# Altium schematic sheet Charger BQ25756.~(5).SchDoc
size A3; SheetNumber: 6; SheetTotal: 7
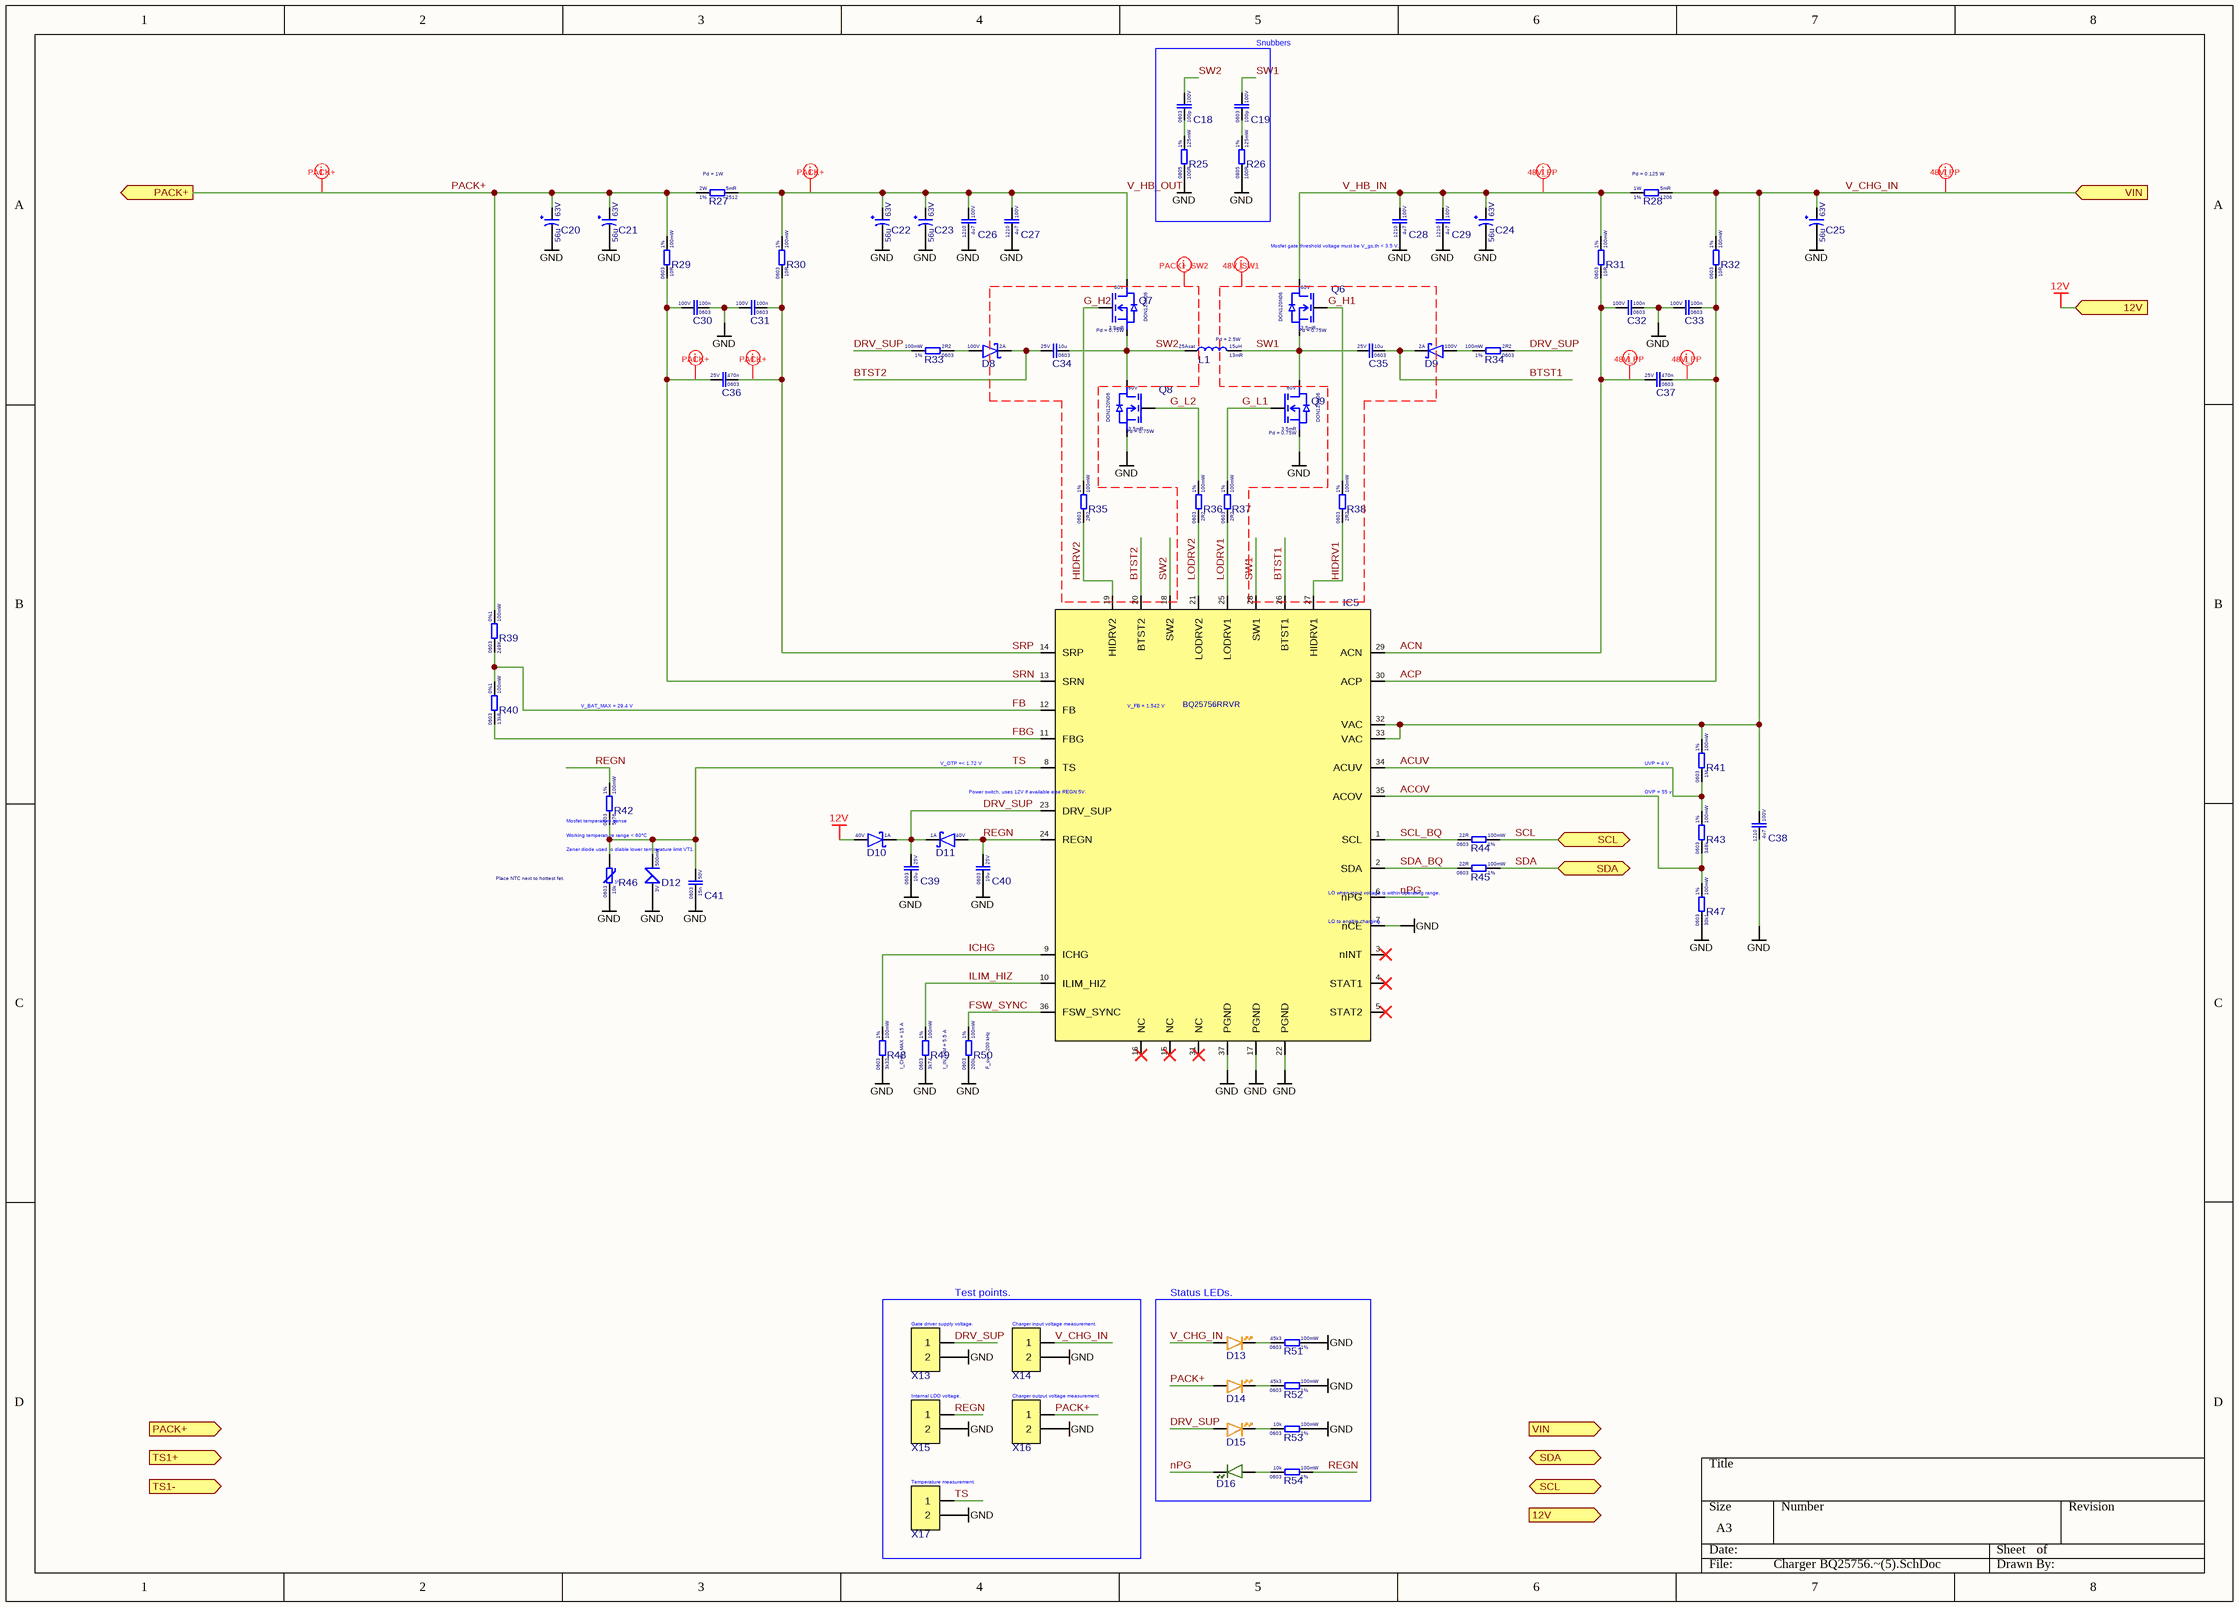
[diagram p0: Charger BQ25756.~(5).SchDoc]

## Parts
C18  Voltage Rating: 100V  Case Code (Imperial): 0603  Capacitance: 100p  [CAP 0603]  (hidden comment: CC0603JRNPO0BN101)
C19  Voltage Rating: 100V  Case Code (Imperial): 0603  Capacitance: 100p  [CAP 0603]  (hidden comment: CC0603JRNPO0BN101)
C20  Voltage Rating: 63V  Capacitance: 56u  [CAP_SMD_10X10.2]  (hidden comment: EEHZA1J560P)
C21  Voltage Rating: 63V  Capacitance: 56u  [CAP_SMD_10X10.2]  (hidden comment: EEHZA1J560P)
C22  Voltage Rating: 63V  Capacitance: 56u  [CAP_SMD_10X10.2]  (hidden comment: EEHZA1J560P)
C23  Voltage Rating: 63V  Capacitance: 56u  [CAP_SMD_10X10.2]  (hidden comment: EEHZA1J560P)
C24  Voltage Rating: 63V  Capacitance: 56u  [CAP_SMD_10X10.2]  (hidden comment: EEHZA1J560P)
C25  Voltage Rating: 63V  Capacitance: 56u  [CAP_SMD_10X10.2]  (hidden comment: EEHZA1J560P)
C26  Voltage Rating: 100V  Case Code (Imperial): 1210  Capacitance: 4u7  [CAP_1210]  (hidden comment: HMK325C7475KN-TE)
C27  Voltage Rating: 100V  Case Code (Imperial): 1210  Capacitance: 4u7  [CAP_1210]  (hidden comment: HMK325C7475KN-TE)
C28  Voltage Rating: 100V  Case Code (Imperial): 1210  Capacitance: 4u7  [CAP_1210]  (hidden comment: HMK325C7475KN-TE)
C29  Voltage Rating: 100V  Case Code (Imperial): 1210  Capacitance: 4u7  [CAP_1210]  (hidden comment: HMK325C7475KN-TE)
C30  Voltage Rating: 100V  Case Code (Imperial): 0603  Capacitance: 100n  [CAP 0603]  (hidden comment: CC0603KRX7R0BB104)
C31  Voltage Rating: 100V  Case Code (Imperial): 0603  Capacitance: 100n  [CAP 0603]  (hidden comment: CC0603KRX7R0BB104)
C32  Voltage Rating: 100V  Case Code (Imperial): 0603  Capacitance: 100n  [CAP 0603]  (hidden comment: CC0603KRX7R0BB104)
C33  Voltage Rating: 100V  Case Code (Imperial): 0603  Capacitance: 100n  [CAP 0603]  (hidden comment: CC0603KRX7R0BB104)
C34  Voltage Rating: 25V  Case Code (Imperial): 0603  Capacitance: 10u  [CAP 0603]  (hidden comment: CL10A106MA8NRNC)
C35  Voltage Rating: 25V  Case Code (Imperial): 0603  Capacitance: 10u  [CAP 0603]  (hidden comment: CL10A106MA8NRNC)
C36  Voltage Rating: 25V  Case Code (Imperial): 0603  Capacitance: 470n  [CAP 0603]  (hidden comment: CL10B474KA8NNNC)
C37  Voltage Rating: 25V  Case Code (Imperial): 0603  Capacitance: 470n  [CAP 0603]  (hidden comment: CL10B474KA8NNNC)
C38  Voltage Rating: 100V  Case Code (Imperial): 1210  Capacitance: 4u7  [CAP_1210]  (hidden comment: HMK325C7475KN-TE)
C39  Voltage Rating: 25V  Case Code (Imperial): 0603  Capacitance: 10u  [CAP 0603]  (hidden comment: CL10A106MA8NRNC)
C40  Voltage Rating: 25V  Case Code (Imperial): 0603  Capacitance: 10u  [CAP 0603]  (hidden comment: CL10A106MA8NRNC)
C41  Voltage Rating: 50V  Case Code (Imperial): 0603  Capacitance: 15n  [CAP 0603]  (hidden comment: CC0603KRX7R9BB153)
D8  Forward Current: 2A  Reverse Voltage: 100V  [SMAF]  (hidden comment: SS210F)
D9  Forward Current: 2A  Reverse Voltage: 100V  [SMAF]  (hidden comment: SS210F)
D10  Forward Current: 1A  Reverse Voltage: 40V  [SOD-323]  (hidden comment: 1N5819WS)
D11  Forward Current: 1A  Reverse Voltage: 40V  [SOD-323]  (hidden comment: 1N5819WS)
D12  Power Rating: 500mW  Reverse Voltage: 3V  [SOD-123]  (hidden comment: BZT52C3V0)
D13  XL-1608UOC-06  [DIODE_0603_ORANGE]  (value not drawn)
D14  XL-1608UOC-06  [DIODE_0603_ORANGE]  (value not drawn)
D15  XL-1608UOC-06  [DIODE_0603_ORANGE]  (value not drawn)
D16  PSC-1608U52GC-G4  [DIODE_0603_GREEN]  (value not drawn)
IC5  BQ25756RRVR  [VQFN-36(5x6)]
L1  Pd = 2.5W  Resistance: 13mR  Saturation current: 25Asat  Inductance: 15uH  [IND 17.5x17.15x7.0]
Q6  Pd = 0.75W  Rds: 3.5mR  Voltage: 60V  [DFN-8 (5x6)]
Q7  Pd = 0.75W  Rds: 3.5mR  Voltage: 60V  [DFN-8 (5x6)]
Q8  Pd = 0.75W  Rds: 3.5mR  Voltage: 60V  [DFN-8 (5x6)]
Q9  Pd = 0.75W  Rds: 3.5mR  Voltage: 60V  [DFN-8 (5x6)]
R25  Resistance Tolerance: 1%  Resistance: 100R  Power Rating: 125mW  Case Code (Imperial): 0805  [Res_0805]  (hidden comment: 0805W8F1000T5E)
R26  Resistance Tolerance: 1%  Resistance: 100R  Power Rating: 125mW  Case Code (Imperial): 0805  [Res_0805]  (hidden comment: 0805W8F1000T5E)
R27  Pd = 1W  Resistance Tolerance: 1%  Resistance: 5mR  Power Rating: 2W  Case Code (Imperial): 2512  [RES_2512]
R28  Pd = 0.125 W  Resistance Tolerance: 1%  Resistance: 5mR  Power Rating: 1W  Case Code (Imperial): 1206  [RES_1206]
R29  Resistance Tolerance: 1%  Resistance: 10R  Power Rating: 100mW  Case Code (Imperial): 0603  [RES_0603]  (hidden comment: 0603WAF100JT5E)
R30  Resistance Tolerance: 1%  Resistance: 10R  Power Rating: 100mW  Case Code (Imperial): 0603  [RES_0603]  (hidden comment: 0603WAF100JT5E)
R31  Resistance Tolerance: 1%  Resistance: 10R  Power Rating: 100mW  Case Code (Imperial): 0603  [RES_0603]  (hidden comment: 0603WAF100JT5E)
R32  Resistance Tolerance: 1%  Resistance: 10R  Power Rating: 100mW  Case Code (Imperial): 0603  [RES_0603]  (hidden comment: 0603WAF100JT5E)
R33  Resistance Tolerance: 1%  Resistance: 2R2  Power Rating: 100mW  Case Code (Imperial): 0603  [RES_0603]  (hidden comment: 0603WAF220KT5E)
R34  Resistance Tolerance: 1%  Resistance: 2R2  Power Rating: 100mW  Case Code (Imperial): 0603  [RES_0603]  (hidden comment: 0603WAF220KT5E)
R35  Resistance Tolerance: 1%  Resistance: 2R2  Power Rating: 100mW  Case Code (Imperial): 0603  [RES_0603]  (hidden comment: 0603WAF220KT5E)
R36  Resistance Tolerance: 1%  Resistance: 2R2  Power Rating: 100mW  Case Code (Imperial): 0603  [RES_0603]  (hidden comment: 0603WAF220KT5E)
R37  Resistance Tolerance: 1%  Resistance: 2R2  Power Rating: 100mW  Case Code (Imperial): 0603  [RES_0603]  (hidden comment: 0603WAF220KT5E)
R38  Resistance Tolerance: 1%  Resistance: 2R2  Power Rating: 100mW  Case Code (Imperial): 0603  [RES_0603]  (hidden comment: 0603WAF220KT5E)
R39  Resistance Tolerance: 0%1  Resistance: 249K  Power Rating: 100mW  Case Code (Imperial): 0603  [RES_0603]  (hidden comment: RT0603BRD07249KL)
R40  Resistance Tolerance: 0%1  Resistance: 13k8  Power Rating: 100mW  Case Code (Imperial): 0603  [RES_0603]  (hidden comment: RT0603BRD0713K8L)
R41  Resistance Tolerance: 1%  Resistance: 1M  Power Rating: 100mW  Case Code (Imperial): 0603  [RES_0603]  (hidden comment: 0603WAF1004T5E)
R42  Resistance Tolerance: 1%  Resistance: 5k76  Power Rating: 100mW  Case Code (Imperial): 0603  [RES_0603]  (hidden comment: 0603WAF5761T5E)
R43  Resistance Tolerance: 1%  Resistance: 348k  Power Rating: 100mW  Case Code (Imperial): 0603  [RES_0603]  (hidden comment: 0603WAF3483T5E)
R44  Resistance Tolerance: 1%  Resistance: 22R  Power Rating: 100mW  Case Code (Imperial): 0603  [RES_0603]  (hidden comment: 0603WAF220JT5E)
R45  Resistance Tolerance: 1%  Resistance: 22R  Power Rating: 100mW  Case Code (Imperial): 0603  [RES_0603]  (hidden comment: 0603WAF220JT5E)
R46  Place NTC next to hottest fet.  Resistance: 10k  Case Code (Imperial): 0603  [RES_0603]
R47  Resistance Tolerance: 1%  Resistance: 30k1  Power Rating: 100mW  Case Code (Imperial): 0603  [RES_0603]  (hidden comment: 0603WAF3012T5E)
R48  I_CHG_MAX = 15 A  Resistance Tolerance: 1%  Resistance: 3k32  Power Rating: 100mW  Case Code (Imperial): 0603  [RES_0603]
R49  I_IN_LIM = 5.5 A  Resistance Tolerance: 1%  Resistance: 3k74  Power Rating: 100mW  Case Code (Imperial): 0603  [RES_0603]
R50  F_sw = 200 kHz  Resistance Tolerance: 1%  Resistance: 200k  Power Rating: 100mW  Case Code (Imperial): 0603  [RES_0603]
R51  Resistance Tolerance: 1%  Resistance: 45k3  Power Rating: 100mW  Case Code (Imperial): 0603  [RES_0603]  (hidden comment: 0603WAF4532T5E)
R52  Resistance Tolerance: 1%  Resistance: 45k3  Power Rating: 100mW  Case Code (Imperial): 0603  [RES_0603]  (hidden comment: 0603WAF4532T5E)
R53  Resistance Tolerance: 1%  Resistance: 10k  Power Rating: 100mW  Case Code (Imperial): 0603  [RES_0603]  (hidden comment: 0603WAF1002T5E)
R54  Resistance Tolerance: 1%  Resistance: 10k  Power Rating: 100mW  Case Code (Imperial): 0603  [RES_0603]  (hidden comment: 0603WAF1002T5E)
X13  ZX-PZ1.27-1-2PZZ  [Pin header 1x2 1.27mmP THT Vertical]  (value not drawn)
X14  ZX-PZ1.27-1-2PZZ  [Pin header 1x2 1.27mmP THT Vertical]  (value not drawn)
X15  ZX-PZ1.27-1-2PZZ  [Pin header 1x2 1.27mmP THT Vertical]  (value not drawn)
X16  ZX-PZ1.27-1-2PZZ  [Pin header 1x2 1.27mmP THT Vertical]  (value not drawn)
X17  ZX-PZ1.27-1-2PZZ  [Pin header 1x2 1.27mmP THT Vertical]  (value not drawn)

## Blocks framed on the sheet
Snubbers: C18 C19 R25 R26
Test points.: X13-X17
Status LEDs.: D13-D16 R51-R54

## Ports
12V (in, see CHARGER[4B]), PACK+ (out, see CHARGER[3B], BMS[8A], CHARGER[1B]), SCL (bidir, see CHARGER[4B], BMS[8C], CHARGER[1D], USB PD[7B]), SDA (bidir, see CHARGER[4B], BMS[8C], CHARGER[1D], USB PD[7B]), TS1+ (in, see CHARGER[3B], CHARGER[1B]), TS1- (in, see CHARGER[3B], CHARGER[1B]), VIN (in, see CHARGER[4B])

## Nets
12V: D10.A ; port 12V
GND: C20.- C21.- C22.- C23.- C24.- C25.- C26.1 C27.1 C28.1 C29.1 C30.1 C31.2 C32.1 C33.2 C38.1 C39.1 C40.1 C41.1 D12.A IC5.7(nCE) IC5.17(PGND) IC5.22(PGND) IC5.37(PGND) Q8.S Q9.S R25.1 R26.1 R46.1 R47.1 R48.1 R49.1 R50.1 R51.2 R52.2 R53.2 X13.2 X14.2 X15.2 X16.2 X17.2
ACN: C32.2 C37.2 IC5.29(ACN) R31.1
ACOV: IC5.35(ACOV) R43.1 R47.2
ACP: C33.1 C37.1 IC5.30(ACP) R32.1
ACUV: IC5.34(ACUV) R41.1 R43.2
BTST1: C35.1 D9.K IC5.26(BTST1)
BTST2: C34.2 D8.K IC5.20(BTST2)
DRV_SUP: C39.2 D10.K D11.K D15.A IC5.23(DRV_SUP) R33.2 R34.1 X13.1
FB: IC5.12(FB) R39.1 R40.2
FBG: IC5.11(FBG) R40.1
FSW_SYNC: IC5.36(FSW_SYNC) R50.2
G_H1: Q6.G R38.2
G_H2: Q7.G R35.2
G_L1: Q9.G R37.2
G_L2: Q8.G R36.2
HIDRV1: IC5.27(HIDRV1) R38.1
HIDRV2: IC5.19(HIDRV2) R35.1
ICHG: IC5.9(ICHG) R48.2
ILIM_HIZ: IC5.10(ILIM_HIZ) R49.2
LODRV1: IC5.25(LODRV1) R37.1
LODRV2: IC5.21(LODRV2) R36.1
nPG: D16.K IC5.6(nPG)
PACK+: C20.+ C21.+ D14.A R27.2 R29.2 R39.2 X16.1 ; port PACK+
REGN: C40.2 D11.A IC5.24(REGN) R42.2 R54.2 X15.1
SCL: R44.2 ; port SCL
SCL_BQ: IC5.1(SCL) R44.1
SDA: R45.2 ; port SDA
SDA_BQ: IC5.2(SDA) R45.1
SRN: C30.2 C36.2 IC5.13(SRN) R29.1
SRP: C31.1 C36.1 IC5.14(SRP) R30.1
SW1: C19.2 C35.2 IC5.28(SW1) L1.1 Q6.S Q9.D
SW2: C18.2 C34.1 IC5.18(SW2) L1.2 Q7.S Q8.D
TS: C41.2 D12.K IC5.8(TS) R42.1 R46.2 X17.1
V_CHG_IN: C25.+ C38.2 D13.A IC5.32(VAC) IC5.33(VAC) R28.1 R32.2 R41.2 X14.1 ; port VIN
V_HB_IN: C24.+ C28.2 C29.2 Q6.D R28.2 R31.2
V_HB_OUT: C22.+ C23.+ C26.2 C27.2 Q7.D R27.1 R30.2
NetC18_1: C18.1 R25.2
NetC19_1: C19.1 R26.2
NetD8_A: D8.A R33.1
NetD9_A: D9.A R34.2
NetD13_K: D13.K R51.1
NetD14_K: D14.K R52.1
NetD15_K: D15.K R53.1
NetD16_A: D16.A R54.1

Not connected (* = marked no-connect by the designer): IC5 3(nINT)* 4(STAT1)* 5(STAT2)* 15(NC)* 16(NC)* 31(NC)*

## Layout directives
net class 48V_PP: ACN, ACP, V_CHG_IN, V_HB_IN
net class PACK+: PACK+, SRN, SRP, V_HB_OUT
net class 48V_SW1: BTST1, G_H1, G_L1, GND, HIDRV1, LODRV1, SW1
net class PACK+_SW2: BTST2, G_H2, G_L2, GND, HIDRV2, LODRV2, SW2

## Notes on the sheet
- Mosfet gate threshold voltage must be V_gs,th < 3.5 V.
- (near R40) V_BAT_MAX = 29.4 V
- V_OTP =< 1.72 V
- (near IC5) V_FB = 1.542 V
- UVP = 4 V
- Mosfet temperature sense
- Working temperature range < 60°C
- Power switch, uses 12V if available else REGN 5V.
- OVP = 55 v
- Zener diode used to diable lower temperature limit VT1.
- (near IC5) LO when input voltage is within operating range.
- (near IC5) LO to enable charging.
- (near X13) Gate driver supply voltage.
- (near X14) Charger input voltage measurement.
- (near X15) Internal LDO voltage.
- (near X16) Charger output voltage measurement.
- (near X17) Temperature measurement.

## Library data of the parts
C18 C19 = CC0603JRNPO0BN101: Cap 100pF 100V 0603 NP0; Manufacturer: Yageo; Manufacturer Part Number: CC0603KRX7R9BB104
C20-C25 = EEHZA1J560P: Cap AL-EL 56uF 63V 30mR 1.8Ar SMD 10x10.2mm; Manufacturer: Panasonic
C26-C29 C38 = HMK325C7475KN-TE: Cap 4.7uF 100V 1210 X7R; Manufacturer: Taiyo Yuden
C30-C33 = CC0603KRX7R0BB104: Cap 100nF 100V 0603 X7R; Manufacturer: YAGEO
C34 C35 C39 C40 = CL10A106MA8NRNC: Cap 10uF 25V 0603 X5R; Manufacturer: Samsung
C36 C37 = CL10B474KA8NNNC: Cap 470nF 25V 0603 X7R; Manufacturer: Samsung
C41 = CC0603KRX7R9BB153: Cap 15nF 50V 0603 X7R; Manufacturer: Yageo; Manufacturer Part Number: CC0603KRX7R9BB104
D8 D9 = SS210F: Schottky 100V 2A 850mVf SMAF; Manufacturer: GOODWORK
D10 D11 = 1N5819WS: Schottky 40V 1A 600mVf SOD-323; Manufacturer: Guangdong Hottech
D12 = BZT52C3V0: Zener 3.0V 500mW SOD-123; Manufacturer: Shandong Jingdao Microelectronics
D13-D15 = XL-1608UOC-06: LED Orange 0603 20mA; Manufacturer: XINGLIGHT
D16 = PSC-1608U52GC-G4: LED Green 0603 20mA; Manufacturer: HONGLITRONIC
IC5 = BQ25756RRVR: Charger IC; Manufacturer: Texas Instruments
L1 = SMMS1770-150M: Inductor 15uH 25Asat 13mR 30V; Manufacturer: SXN
Q6-Q9 = DON120N06: Nmos 60V 120A 3.5mR 1120pF DFN-8(5x6); Manufacturer: DOINGTER
R25 R26 = 0805W8F1000T5E: Res 100R 0805 1% 125mW 150V; Manufacturer: UNI-ROYAL
R27 = RLM25FEER005: Res 5mR 2512 1% 2W; Manufacturer: TA-I Tech
R28 = FRM121WFR005TM: Res 5mR 1206 1% 1W; Manufacturer: FOJAN
R29-R32 = 0603WAF100JT5E: Res 10R 0603 1% 100mW 75V; Manufacturer: Uni-Royal
R33-R38 = 0603WAF220KT5E: Res 2R2 0603 1% 100mW 75V; Manufacturer: Uni-Royal
R39 = RT0603BRD07249KL: Res 249K 0603 0.1% 100mW 75V; Manufacturer: YAGEO
R40 = RT0603BRD0713K8L: Res 13.8k 0603 0.1% 100mW 75V; Manufacturer: YAGEO
R41 = 0603WAF1004T5E: Res 1M 0603 1% 100mW 75V; Manufacturer: Uni-Royal
R42 = 0603WAF5761T5E: Res 5k76 0603 1% 100mW 75V; Manufacturer: Uni-Royal
R43 = 0603WAF3483T5E: Res 348k 0603 1% 100mW 75V; Manufacturer: Uni-Royal
R44 R45 = 0603WAF220JT5E: Res 22R 0603 1% 100mW 75V; Manufacturer: Uni-Royal
R46 = NCP18XH103F03RB: NTC 10k 0603 1% 3455K; Manufacturer: Murata
R47 = 0603WAF3012T5E: Res 30k1 0603 1% 100mW 75V; Manufacturer: Uni-Royal
R48 = 0603WAF3321T5E: Res 3k32 0603 1% 100mW 75V; Manufacturer: UNI-ROYAL
R49 = FRC0603F3741TS: Res 3K74 0603 1% 100mW 75V; Manufacturer: FOJAN
R50 = 0603WAF2003T5E: Res 200K 0603 1% 100mW 75V; Manufacturer: UNI-ROYAL
R51 R52 = 0603WAF4532T5E: Res 45k3 0603 1% 100mW 75V; Manufacturer: Uni-Royal
R53 R54 = 0603WAF1002T5E: Res 10k 0603 1% 100mW 75V; Manufacturer: Uni-Royal
X13-X17 = ZX-PZ1.27-1-2PZZ: Pin header 1x2 1.27mmP THT Vertical; Manufacturer: Megastar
